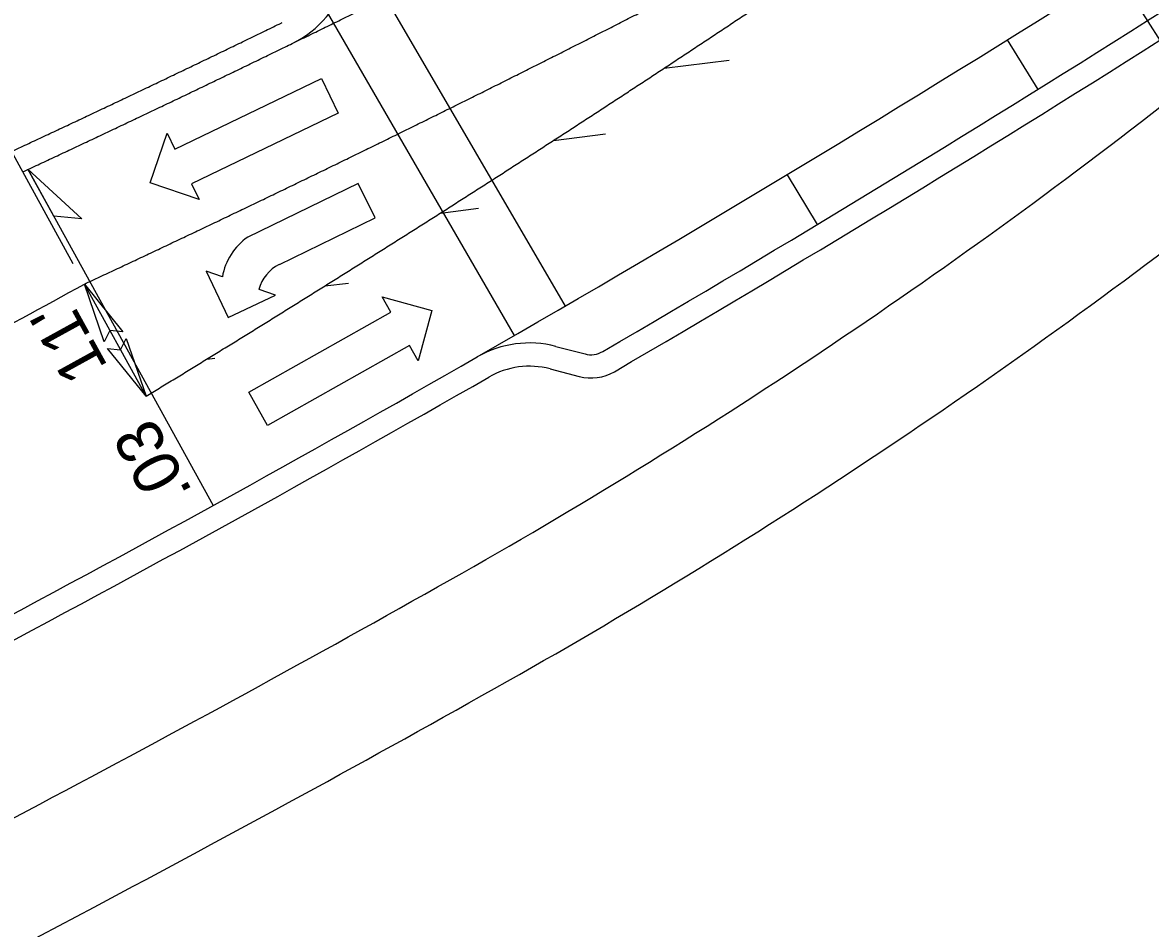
# Model space of a CAD drawing. Extents: x 1486489 to 1490134, y 497089 to 500876.
# Drawn here: x 1488126 to 1488222.9, y 498502.1 to 498579.9 of the extents above; entities that cross this region are included whole.
import ezdxf

# ---------------------------------------------------------------- set-up
doc = ezdxf.new("R2010")
doc.units = 0
for name, color, linetype in [('Prop Horizontal Alignment Station Label', 7, 'Continuous'), ('Scratch_Level_3', 7, 'Continuous'), ('Scratch_Level_5', 7, 'Continuous'), ('Sheet Block Title CELL', 7, 'Continuous'), ('Sheet Border Standard 30in CELL', 7, 'Continuous'), ('Sheet Cutting Line CELL', 7, 'Continuous'), ('Sheet Plot Border Inside CELL', 7, 'Continuous'), ('Sheet Plot Border Outside CELL', 7, 'Continuous'), ('Sheet Sticker Exception Certification CELL', 7, 'Continuous'), ('Sheet Sticker Incomplete CELL', 7, 'Continuous'), ('Sheet Title CELL', 7, 'Continuous')]:
    doc.layers.add(name, color=color, linetype=linetype)

msp = doc.modelspace()

# ---------------------------------------------------------------- linework, layer by layer
at = {"layer": 'Prop Horizontal Alignment Station Label'}
for p, q in [((1488077.522, 498486.323), (1488127.445, 498512.75)), ((1488082.201, 498477.485), (1488132.124, 498503.912))]:
    msp.add_line(p, q, dxfattribs=at)
for centre, radius, start, end in [((1487919.498, 498963.156), 495, 299.42864, 308.08818), ((1487919.498, 498963.156), 505, 299.42864, 308.08818), ((1487424.965, 499839.786), 1501.5, 297.894972, 299.428645), ((1487424.965, 499839.786), 1511.5, 297.894972, 299.428645)]:
    msp.add_arc(centre, radius, start, end, dxfattribs=at)
at = {"layer": 'Scratch_Level_3'}
msp.add_line((1488126.423, 498567.321), (1488142.354, 498538.422), dxfattribs=at)
msp.add_lwpolyline([(1488126.423, 498567.321), (1488131.071, 498563.032), (1488128.656, 498563.271)], close=True, dxfattribs=at)
at = {"layer": 'Scratch_Level_5'}
msp.add_line((1488171.283, 498550.152), (1488173.788, 498549.498), dxfattribs=at)
for centre, radius, start, end in [((1487424.965, 499839.786), 1493, 300.237276, 304.446703), ((1488169.515, 498543.379), 7, 75.36946, 119.86952), ((1488174.799, 498553.368), 4, 255.36946, 300.23728), ((1487424.965, 499839.786), 1488, 297.894972, 299.869525)]:
    msp.add_arc(centre, radius, start, end, dxfattribs=at)
msp.add_spline([(1488125.009, 498568.826), (1488125.674, 498569.135), (1488126.338, 498569.445), (1488127.002, 498569.756), (1488127.666, 498570.066), (1488128.329, 498570.377), (1488128.993, 498570.688), (1488129.657, 498571), (1488130.32, 498571.312), (1488130.983, 498571.624), (1488131.646, 498571.937), (1488132.309, 498572.25), (1488132.972, 498572.563), (1488133.634, 498572.877), (1488134.297, 498573.191), (1488134.959, 498573.505), (1488135.622, 498573.82), (1488136.284, 498574.135), (1488136.946, 498574.45), (1488137.607, 498574.766), (1488138.269, 498575.082), (1488138.931, 498575.399), (1488139.592, 498575.715), (1488140.253, 498576.033), (1488140.914, 498576.35), (1488141.575, 498576.668), (1488142.236, 498576.986), (1488142.897, 498577.305), (1488143.558, 498577.623), (1488144.218, 498577.943), (1488144.878, 498578.262), (1488145.539, 498578.582), (1488146.199, 498578.902), (1488146.858, 498579.223), (1488147.518, 498579.544), (1488148.178, 498579.865), (1488148.271, 498579.91)], degree=3, dxfattribs=at)
at = {"layer": 'Sheet Block Title CELL'}
for p, q in [((1488210.548, 498578.415), (1488213.191, 498574.171)), ((1488181.1, 498576), (1488186.684, 498576.69)), ((1488171.587, 498569.785), (1488176.047, 498570.337)), ((1488191.647, 498566.839), (1488194.227, 498562.556)), ((1488161.872, 498563.545), (1488165.147, 498563.95)), ((1488151.944, 498557.279), (1488153.967, 498557.53)), ((1488141.792, 498550.986), (1488142.49, 498551.072))]:
    msp.add_line(p, q, dxfattribs=at)
for radius, start, end in [(1486, 299.869525, 304.814454), (1464, 297.894972, 298.845976)]:
    msp.add_arc((1487424.965, 499839.786), radius, start, end, dxfattribs=at)
for points in [[(1488178.858, 498574.526), (1488179.423, 498574.896), (1488179.987, 498575.267), (1488180.551, 498575.638), (1488181.115, 498576.01), (1488181.679, 498576.381), (1488182.243, 498576.753), (1488182.806, 498577.125), (1488183.369, 498577.498), (1488183.932, 498577.87), (1488184.495, 498578.243), (1488185.058, 498578.616), (1488185.62, 498578.99), (1488186.183, 498579.363), (1488186.745, 498579.737), (1488187.307, 498580.111), (1488187.869, 498580.486), (1488188.43, 498580.86), (1488188.992, 498581.235), (1488189.553, 498581.61), (1488190.114, 498581.986), (1488190.675, 498582.362), (1488191.236, 498582.737), (1488191.796, 498583.114), (1488192.356, 498583.49), (1488192.916, 498583.867), (1488193.476, 498584.243), (1488194.036, 498584.621), (1488194.596, 498584.998), (1488195.155, 498585.376), (1488195.714, 498585.754), (1488196.273, 498586.132), (1488196.832, 498586.51), (1488197.391, 498586.889), (1488197.949, 498587.268), (1488198.508, 498587.647), (1488199.066, 498588.026), (1488199.624, 498588.406), (1488200.181, 498588.786), (1488200.739, 498589.166), (1488201.296, 498589.546), (1488201.854, 498589.927), (1488202.411, 498590.308), (1488202.967, 498590.689), (1488203.524, 498591.07), (1488204.08, 498591.452), (1488204.637, 498591.834), (1488205.193, 498592.216), (1488205.749, 498592.598), (1488206.304, 498592.981), (1488206.86, 498593.364), (1488207.415, 498593.747), (1488207.97, 498594.13), (1488208.525, 498594.514), (1488209.08, 498594.897), (1488209.634, 498595.281), (1488210.189, 498595.666), (1488210.743, 498596.05), (1488211.297, 498596.435), (1488211.851, 498596.82), (1488212.405, 498597.206), (1488212.958, 498597.591), (1488213.511, 498597.977), (1488214.064, 498598.363), (1488214.617, 498598.749), (1488215.17, 498599.136), (1488215.722, 498599.523), (1488216.275, 498599.91), (1488216.827, 498600.297), (1488217.379, 498600.685), (1488217.93, 498601.072), (1488218.482, 498601.46), (1488219.033, 498601.849), (1488220.136, 498602.626)], [(1488149.145, 498578.117), (1488150.494, 498578.775), (1488151.154, 498579.098), (1488151.814, 498579.421), (1488152.474, 498579.745), (1488153.133, 498580.068), (1488153.793, 498580.393), (1488154.452, 498580.717), (1488155.111, 498581.042), (1488155.77, 498581.367), (1488156.429, 498581.693), (1488157.088, 498582.019), (1488157.747, 498582.345), (1488158.405, 498582.672), (1488159.064, 498582.999), (1488159.722, 498583.326), (1488160.38, 498583.654), (1488161.038, 498583.982), (1488161.696, 498584.31), (1488162.353, 498584.639), (1488163.011, 498584.968), (1488163.668, 498585.297), (1488164.325, 498585.627), (1488164.982, 498585.957), (1488165.639, 498586.287), (1488166.296, 498586.618), (1488166.953, 498586.949), (1488167.609, 498587.28), (1488168.265, 498587.612), (1488168.922, 498587.944), (1488169.578, 498588.277), (1488170.234, 498588.609), (1488170.889, 498588.943), (1488171.545, 498589.276), (1488172.2, 498589.61), (1488172.856, 498589.944), (1488173.511, 498590.279), (1488174.166, 498590.613), (1488174.821, 498590.949)], [(1488131.281, 498557.439), (1488131.951, 498557.752), (1488132.621, 498558.065), (1488133.291, 498558.378), (1488133.961, 498558.692), (1488134.63, 498559.006), (1488135.299, 498559.32), (1488135.969, 498559.635), (1488136.638, 498559.95), (1488137.307, 498560.266), (1488137.975, 498560.582), (1488138.644, 498560.898), (1488139.312, 498561.214), (1488139.981, 498561.531), (1488140.649, 498561.848), (1488141.317, 498562.166), (1488141.985, 498562.484), (1488142.653, 498562.802), (1488143.321, 498563.121), (1488143.988, 498563.44), (1488144.655, 498563.759), (1488145.323, 498564.079), (1488145.99, 498564.399), (1488146.657, 498564.719), (1488147.324, 498565.04), (1488147.99, 498565.361), (1488148.657, 498565.682), (1488149.323, 498566.004), (1488149.99, 498566.326), (1488150.656, 498566.649), (1488151.322, 498566.971), (1488151.988, 498567.294), (1488152.653, 498567.618), (1488153.319, 498567.942), (1488153.984, 498568.266), (1488154.65, 498568.591), (1488155.315, 498568.915), (1488155.98, 498569.241), (1488156.645, 498569.566), (1488157.309, 498569.892), (1488157.974, 498570.218), (1488158.638, 498570.545), (1488159.303, 498570.872), (1488159.967, 498571.199), (1488160.631, 498571.527), (1488161.295, 498571.855), (1488161.958, 498572.183), (1488162.622, 498572.512), (1488163.285, 498572.841), (1488163.949, 498573.17), (1488164.612, 498573.5), (1488165.275, 498573.83), (1488165.938, 498574.161), (1488166.6, 498574.492), (1488167.263, 498574.823), (1488167.925, 498575.154), (1488168.587, 498575.486), (1488169.25, 498575.818), (1488169.912, 498576.151), (1488170.573, 498576.484), (1488171.235, 498576.817), (1488171.897, 498577.15), (1488172.558, 498577.484), (1488173.219, 498577.818), (1488173.88, 498578.153), (1488174.541, 498578.488), (1488175.202, 498578.823), (1488175.863, 498579.159), (1488176.523, 498579.495), (1488177.184, 498579.831), (1488177.844, 498580.168), (1488178.504, 498580.505), (1488179.164, 498580.842), (1488179.824, 498581.18), (1488180.483, 498581.518)], [(1488136.588, 498547.804), (1488137.166, 498548.156), (1488137.744, 498548.508), (1488138.321, 498548.86), (1488138.898, 498549.212), (1488139.475, 498549.565), (1488140.052, 498549.918), (1488140.628, 498550.272), (1488141.205, 498550.625), (1488141.781, 498550.979), (1488142.357, 498551.333), (1488142.933, 498551.687), (1488143.508, 498552.042), (1488144.084, 498552.397), (1488144.659, 498552.752), (1488145.235, 498553.107), (1488145.81, 498553.463), (1488146.384, 498553.819), (1488146.959, 498554.175), (1488147.534, 498554.531), (1488148.108, 498554.888), (1488148.682, 498555.245), (1488149.256, 498555.602), (1488149.83, 498555.959), (1488150.403, 498556.317), (1488150.977, 498556.675), (1488151.55, 498557.033), (1488152.123, 498557.392), (1488152.696, 498557.75), (1488153.269, 498558.109), (1488153.841, 498558.469), (1488154.414, 498558.828), (1488154.986, 498559.188), (1488155.558, 498559.548), (1488156.13, 498559.908), (1488156.702, 498560.268), (1488157.273, 498560.629), (1488157.844, 498560.99), (1488158.416, 498561.351), (1488158.987, 498561.713), (1488159.557, 498562.075), (1488160.128, 498562.437), (1488160.698, 498562.799), (1488161.269, 498563.162), (1488161.839, 498563.524), (1488162.409, 498563.887), (1488162.978, 498564.251), (1488163.548, 498564.614), (1488164.117, 498564.978), (1488164.687, 498565.342), (1488165.256, 498565.706), (1488165.824, 498566.071), (1488166.393, 498566.436), (1488166.962, 498566.801), (1488167.53, 498567.166), (1488168.098, 498567.532), (1488168.666, 498567.898), (1488169.234, 498568.264), (1488169.801, 498568.63), (1488170.369, 498568.997), (1488170.936, 498569.363), (1488171.503, 498569.73), (1488172.07, 498570.098), (1488172.637, 498570.465), (1488173.203, 498570.833), (1488173.769, 498571.201), (1488174.336, 498571.57), (1488174.901, 498571.938), (1488175.467, 498572.307), (1488176.033, 498572.676), (1488176.598, 498573.046), (1488177.164, 498573.415), (1488177.729, 498573.785), (1488178.293, 498574.155), (1488178.858, 498574.526)]]:
    msp.add_spline(points, degree=3, dxfattribs=at)
at = {"layer": 'Sheet Border Standard 30in CELL'}
for p, q in [((1488154.633, 498586.37), (1488172.577, 498555.546)), ((1488168.219, 498553.019), (1488150.213, 498584.192))]:
    msp.add_line(p, q, dxfattribs=at)
at = {"layer": 'Sheet Cutting Line CELL'}
for p, q in [((1488130.316, 498559.191), (1488080.789, 498649.11)), ((1488136.588, 498547.804), (1488131.281, 498557.439))]:
    msp.add_line(p, q, dxfattribs=at)
at = {"layer": 'Sheet Plot Border Inside CELL'}
for p, q in [((1488139.05, 498569.041), (1488151.665, 498575.112)), ((1488151.665, 498575.112), (1488153.096, 498572.139)), ((1488153.096, 498572.139), (1488140.481, 498566.067)), ((1488136.948, 498566.143), (1488138.399, 498570.393)), ((1488138.399, 498570.393), (1488139.05, 498569.041)), ((1488141.131, 498564.716), (1488136.948, 498566.143)), ((1488140.481, 498566.067), (1488141.131, 498564.716)), ((1488154.803, 498566.095), (1488145.326, 498561.458)), ((1488156.253, 498563.131), (1488154.803, 498566.095)), ((1488148.035, 498559.109), (1488156.253, 498563.131)), ((1488143.151, 498558.055), (1488141.746, 498558.537)), ((1488141.746, 498558.537), (1488143.635, 498554.562)), ((1488147.699, 498556.496), (1488146.295, 498556.977)), ((1488143.635, 498554.562), (1488147.699, 498556.496)), ((1488157.599, 498555.03), (1488156.863, 498556.336)), ((1488156.863, 498556.336), (1488161.129, 498555.183)), ((1488145.405, 498548.153), (1488157.599, 498555.03)), ((1488161.129, 498555.183), (1488159.957, 498550.848)), ((1488159.22, 498552.155), (1488147.025, 498545.279)), ((1488159.957, 498550.848), (1488159.22, 498552.155)), ((1488147.025, 498545.279), (1488145.405, 498548.153))]:
    msp.add_line(p, q, dxfattribs=at)
for centre, radius, start, end in [((1488148.313, 498557.157), 5.253, 124.75286, 170.06456), ((1488149.457, 498556.178), 3.275, 116.07679, 165.73497)]:
    msp.add_arc(centre, radius, start, end, dxfattribs=at)
at = {"layer": 'Sheet Plot Border Outside CELL'}
for points in [[(1488132.997, 498552.476), (1488131.281, 498557.439), (1488134.598, 498553.325), (1488133.473, 498553.46)], [(1488134.872, 498552.767), (1488136.588, 498547.804), (1488133.272, 498551.918), (1488134.397, 498551.783)]]:
    msp.add_lwpolyline(points, close=True, dxfattribs=at)
at = {"layer": 'Sheet Sticker Exception Certification CELL'}
msp.add_line((1488171.788, 498552.087), (1488174.293, 498551.433), dxfattribs=at)
for centre, radius, start, end in [((1487424.965, 499839.786), 1491, 300.237276, 304.446703), ((1488145.201, 498586.207), 9, 295.98816, 343.56972), ((1488169.515, 498543.379), 9, 75.36946, 119.86952), ((1487424.965, 499839.786), 1486, 297.894972, 299.869525), ((1488174.799, 498553.368), 2, 255.36946, 300.23728)]:
    msp.add_arc(centre, radius, start, end, dxfattribs=at)
msp.add_spline([(1488125.974, 498567.074), (1488126.64, 498567.384), (1488127.305, 498567.694), (1488127.969, 498568.005), (1488128.634, 498568.316), (1488129.299, 498568.628), (1488129.963, 498568.939), (1488130.628, 498569.251), (1488131.292, 498569.564), (1488131.956, 498569.877), (1488132.62, 498570.19), (1488133.284, 498570.503), (1488133.947, 498570.817), (1488134.611, 498571.131), (1488135.274, 498571.446), (1488135.937, 498571.761), (1488136.601, 498572.076), (1488137.264, 498572.391), (1488137.926, 498572.707), (1488138.589, 498573.024), (1488139.252, 498573.34), (1488139.914, 498573.657), (1488140.576, 498573.974), (1488141.238, 498574.292), (1488141.901, 498574.61), (1488142.562, 498574.928), (1488143.224, 498575.247), (1488143.886, 498575.566), (1488144.547, 498575.885), (1488145.208, 498576.205), (1488145.87, 498576.525), (1488146.531, 498576.845), (1488147.192, 498577.166), (1488147.852, 498577.487), (1488148.513, 498577.809), (1488149.145, 498578.117)], degree=3, dxfattribs=at)
at = {"layer": 'Sheet Sticker Incomplete CELL'}
msp.add_line((1488240.797, 498551.359), (1488187.299, 498635.846), dxfattribs=at)

# ---------------------------------------------------------------- texts
at = {"layer": 'Scratch_Level_3'}
msp.add_text('.03', height=4, rotation=117.89497, dxfattribs=at).set_placement((1488140.618, 498539.564))
at = {"layer": 'Sheet Title CELL'}
msp.add_text("11'", height=4, rotation=118.84598, dxfattribs=at).set_placement((1488133.352, 498550.328))

doc.saveas('drawing.dxf')
